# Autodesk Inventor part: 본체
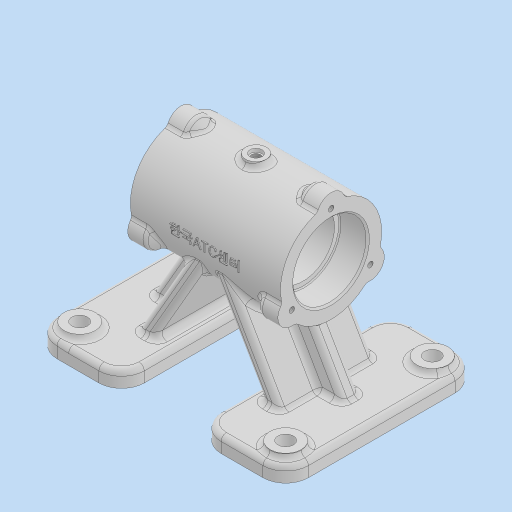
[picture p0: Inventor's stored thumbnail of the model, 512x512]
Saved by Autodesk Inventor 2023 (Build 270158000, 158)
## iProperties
Created: 2026-04
Part Number: 본체
Material: 일반
Document SubType Name: Modeling
Designer: home
Density: 1 g/cm^3
Appearance: 기본값
Mass: 276.559 g
Surface Area: 672.122 cm^2
Volume: 276.559 cm^3
Author: home
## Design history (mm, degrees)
sketch "스케치2"
  geometry: L1 (-43, 29)-(43, 29); L2 (43, 29)-(43, 0); L3 (43, 0)-(-43, 0); L4 (-43, 0)-(-43, 29); 2 further points
  constraints: 8 end point, 2 parallel, 1 coincident, 1 horizontal, 1 midpoint, 1 perpendicular
  dimensions: "d0" = 86 distance of L1.start L1.end; "d1" = 58 diameter of L1 L3
revolve "회전1" sketch "스케치2" stored, may be unused: angle "d6" = 90 deg
node "작업 평면1"
sketch "스케치3"
  geometry: L1 (72, 55)-(22, 55); L2 (22, 55)-(22, -55); L3 (22, -55)-(72, -55); L4 (72, -55)-(72, 55); L5 (72, 55)-(22, -55); L6 (22, 55)-(72, -55); L7 (-22, 55)-(-72, 55); L8 (-72, 55)-(-72, -55); L9 (-72, -55)-(-22, -55); L10 (-22, -55)-(-22, 55); L11 (-22, 55)-(-72, -55); L12 (-72, 55)-(-22, -55); 4 further points
  constraints: 24 end point, 5 midpoint, 4 parallel, 2 collinear, 2 horizontal, 2 perpendicular, 1 horizontal alignment
  dimensions: "d8" = 144 distance between parallel lines of L8 L4; "d9" = 110 distance of L3.end L1.start; "d11" = 50 distance of L1.start L1.end; "d12" = 50 distance of L7.start L7.end; "d13" = 72 distance of point (72, 0) point (0, 0) (= 0.5 x d8)
extrude "돌출1" join sketch "스케치3" distance "d14" = 9; taper "d15" = 0 deg
fillet "모깎기1" dims "d16" = 13
node "작업 평면2"
sketch "스케치6"
  geometry: L1 (43, 10.583)-(43, -10.583) reference; L2 (43, -10.583)-(-43, -10.583) reference; L3 (-43, -10.583)-(-43, 10.583) reference; L4 (-43, 10.583)-(43, 10.583) reference; L5 (22, -63)-(72, -63) reference; L6 (72, -63)-(72, -72) reference; L7 (72, -72)-(22, -72) reference; L8 (22, -72)-(22, -63) reference; L9 (-72, -72)-(-72, -63) reference; L10 (-72, -63)-(-22, -63) reference; L11 (-22, -63)-(-22, -72) reference; L12 (-22, -72)-(-72, -72) reference; L13 (1.737, -10.583)-(32, -63); L14 (59, -63)-(35, -63) reference; L15 (41.238, -63)-(10.975, -10.583); 3 further points
  constraints: 4 end point, 4 point on line, 1 parallel
  dimensions: "d25" = 30 deg angle of L3 L13; "d26" = 10 distance of L5.start L13.end; "d27" = 8 distance between parallel lines of L13 L15
extrude "돌출3" join sketch "스케치6" distance "d28" = 54; taper "d29" = 0 deg
sketch "스케치7"
  geometry: L1 (-72, -72)-(-72, -63) reference; L2 (-72, -63)-(-22, -63) reference; L3 (-22, -63)-(-22, -72) reference; L4 (-22, -72)-(-72, -72) reference; L5 (43, 29)-(43, -29) reference; L6 (43, -29)-(21.608, -29) reference; L7 (21.608, -29)-(41.238, -63) reference; L8 (41.238, -63)-(72, -63) reference; L9 (72, -63)-(72, -72) reference; L10 (72, -72)-(22, -72) reference; L11 (22, -72)-(22, -63) reference; L12 (22, -63)-(32, -63) reference; L13 (32, -63)-(12.37, -29) reference; L14 (12.37, -29)-(-43, -29) reference; L15 (-43, -29)-(-43, 29) reference; L16 (-43, 29)-(43, 29) reference; L17 (59, -63)-(35, -63) reference; L18 (43, -29)-(-43, -29) reference; L19 (55.094, -63)-(18.721, 0); L20 (41.238, -63)-(10.975, -10.583) reference; 1 further point
  constraints: 2 end point, 1 horizontal alignment, 1 parallel, 1 point on line
  dimensions: "d31" = 12 distance between parallel lines of L20 L19
feature "리브1" sketch "스케치7" dims "d32" = 12, "d33" = 10, "d34" = 0, "d35" = 0, "d36" = 1, "d37" = 1
sketch "스케치10"
  geometry: L1 (-32, 27)-(-32, -27) reference; L2 (-32, -27)-(-41.238, -27) reference; L3 (-41.238, -27)-(-41.238, -5) reference; L4 (-41.238, -5)-(-55.094, -5) reference; L5 (-55.094, -5)-(-55.094, 5) reference; L6 (-55.094, 5)-(-41.238, 5) reference; L7 (-41.238, 5)-(-41.238, 27) reference; L8 (-41.238, 27)-(-32, 27) reference; L9 (32, -27)-(32, 27) reference; L10 (32, 27)-(41.238, 27) reference; L11 (41.238, 27)-(41.238, 5) reference; L12 (41.238, 5)-(55.094, 5) reference; L13 (55.094, 5)-(55.094, -5) reference; L14 (55.094, -5)-(41.238, -5) reference; L15 (41.238, -5)-(41.238, -27) reference; L16 (41.238, -27)-(32, -27) reference; L17 (22, -42)-(22, 42) reference; L18 (35, 55)-(59, 55) reference; L19 (72, 42)-(72, -42) reference; L20 (59, -55)-(35, -55) reference; L21 (-22, 42)-(-22, -42) reference; L22 (-35, -55)-(-59, -55) reference; L23 (-72, -42)-(-72, 42) reference; L24 (-59, 55)-(-35, 55) reference; C1 r 9 at (-59, 42); C2 r 9 at (-59, -42); C3 r 9 at (59, 42); C4 r 9 at (59, -42); A1 r 13 centre (35, -42) between (22, -42) and (35, -55) reference; A2 r 13 centre (35, 42) between (35, 55) and (22, 42) reference; A3 r 13 centre (59, 42) between (72, 42) and (59, 55) reference; A4 r 13 centre (59, -42) between (59, -55) and (72, -42) reference; A5 r 13 centre (-35, 42) between (-22, 42) and (-35, 55) reference; A6 r 13 centre (-35, -42) between (-35, -55) and (-22, -42) reference; A7 r 13 centre (-59, -42) between (-72, -42) and (-59, -55) reference; A8 r 13 centre (-59, 42) between (-59, 55) and (-72, 42) reference
  constraints: 4 centre point, 4 coincident
  dimensions: "d52" = 18 diameter of C1; "d54" = 18 diameter of C2; "d57" = 18 diameter of C4; "d59" = 18 diameter of C3
extrude "돌출4" join sketch "스케치10" distance "d60" = 3; taper "d61" = 0 deg
sketch "스케치11"
  geometry: C1 r 9 at (0, 0) reference; C2 r 9 at (0, -84) reference; C3 r 9 at (118, -84) reference; C4 r 9 at (118, 0) reference; 5 further points
  constraints: 4 coincident
hole "구멍3" sketch "스케치11" at (0, 0), (0, -84), (118, -84), (118, 0) diameter "d62" = 9; stored, may be unused: countersink angle "d66" = 90 deg, drill point angle "d68" = 0 deg; dims "d63" = 6, "d64" = 42, "d65" = 16, "d67" = 8
sketch "스케치12"
  geometry: L1 (43, 29)-(-43, 29) reference; L2 (43, 29)-(43, -29) reference; L3 (43, 26)-(-43, 26); L4 (-43, 29)-(-43, -29) reference; L5 (25, 26)-(33, 34); L6 (33, 34)-(43, 34); L7 (43, 34)-(43, 26); 3 further points
  constraints: 8 end point, 3 point on line, 2 horizontal, 1 perpendicular
  dimensions: "d70" = 26 distance from line of L3 point (0, 0); "d71" = 45 deg angle of L4 L5; "d72" = 10 distance of L5.end L6.end; "d73" = 8 distance of L6.end L3.start
revolve "회전2" sketch "스케치12" stored, may be unused: angle "d74" = 90 deg
sketch "스케치8"
  geometry: A1 r 29 centre (0, 0) between (-7.761, 27.942) and (7.761, 27.942) reference; 2 further points
  constraints: 1 coincident
hole "구멍1" sketch "스케치8" at (0, 0) diameter "d38" = 36; stored, may be unused: countersink angle "d42" = 90 deg, drill point angle "d44" = 0 deg; dims "d39" = 12, "d40" = 42, "d41" = 16, "d43" = 14
sketch "스케치9"
  geometry: A1 r 29 centre (0, 0) between (-7.761, 27.942) and (-28.079, -7.25) reference; 2 further points
  constraints: 1 coincident
hole "구멍2" sketch "스케치9" at (0, 0) diameter "d45" = 36; stored, may be unused: countersink angle "d49" = 90 deg, drill point angle "d51" = 0 deg; dims "d46" = 6, "d47" = 42, "d48" = 16, "d50" = 8
sketch "스케치13"
  geometry: A1 r 8 centre (0, 0) between (7.761, 1.942) and (-7.761, 1.942) reference; A2 r 8 centre (-22.517, -39) between (-28.079, -33.25) and (-20.318, -46.692) reference; A3 r 8 centre (22.517, -39) between (20.318, -46.692) and (28.079, -33.25) reference; 4 further points
  constraints: 3 coincident
hole "구멍4" sketch "스케치13" at (0, 0), (-22.517, -39), (22.517, -39) diameter "d78" = 3.242; stored, may be unused: countersink angle "d82" = 90 deg, drill point angle "d84" = 118 deg; dims "d79" = 8, "d80" = 4, "d81" = 2, "d83" = 10
sketch "스케치14"
  geometry: A1 r 8 centre (0, 26) between (7.761, 27.942) and (-7.761, 27.942) reference; A2 r 8 centre (22.517, -13) between (20.318, -20.692) and (28.079, -7.25) reference; A3 r 8 centre (-22.517, -13) between (-28.079, -7.25) and (-20.318, -20.692) reference; 4 further points
  constraints: 3 coincident
hole "구멍5" sketch "스케치14" at (0, 26), (22.517, -13), (-22.517, -13) diameter "d85" = 3.242; stored, may be unused: countersink angle "d89" = 90 deg, drill point angle "d91" = 118 deg; dims "d86" = 8, "d87" = 4, "d88" = 2, "d90" = 10
node "작업 평면4"
sketch "스케치15"
  geometry: C1 r 6 at (0, 0); 1 further point
  constraints: 1 centre point, 1 coincident
  dimensions: "d93" = 12 diameter of C1
extrude "돌출5" join sketch "스케치15" stored distance "d94" = 10; taper "d95" = 0 deg
sketch "스케치16"
  geometry: C1 r 6 at (0, 0) reference; 2 further points
  constraints: 1 coincident
hole "구멍6" sketch "스케치16" at (0, 0) diameter "d96" = 5.1881; stored, may be unused: countersink angle "d100" = 90 deg, drill point angle "d102" = 0 deg; dims "d97" = 12, "d98" = 7, "d99" = 2, "d101" = 10
fillet "모깎기4" dims "d105" = 3
fillet "모깎기2" dims "d103" = 3
fillet "모깎기3" dims "d104" = 3
fillet "모깎기5" dims "d106" = 0.6
chamfer "모따기1" distance "d107" = 1; stored, may be unused: second distance "d108" = 2, angle "d109" = 45 deg
node "작업 평면5"
sketch "스케치17"
  geometry: L1 (-59, -72)-(-35, -72) reference; 2 further points
  constraints: 1 coincident, 1 other
  dimensions: "d110" = 72 distance from line of L1 point (0, 0)
feature "엠보싱1" sketch "스케치17" dims "d0" = 86, "d1" = 58, "d111" = 0.5, "d112" = 0
node "솔리드1"
mirror "미러1"
pattern_circular "원형 패턴1" dims angle "d76" = 360 deg
mirror "미러2"
mirror "미러3"
node "절단 모서리 투영1"
node "절단 모서리 투영2"
node "절단 모서리 투영3"
feature "A9D066F2-1C7D-4E18-AEED-F7BC21143FA4" dims "d62" = 9, "d63" = 6, "d64" = 42, "d65" = 16, "d66" = 90 deg, "d67" = 8, "d68" = 0
other parameters: "d7" = -72, "d24" = 27, "d92" = 32
